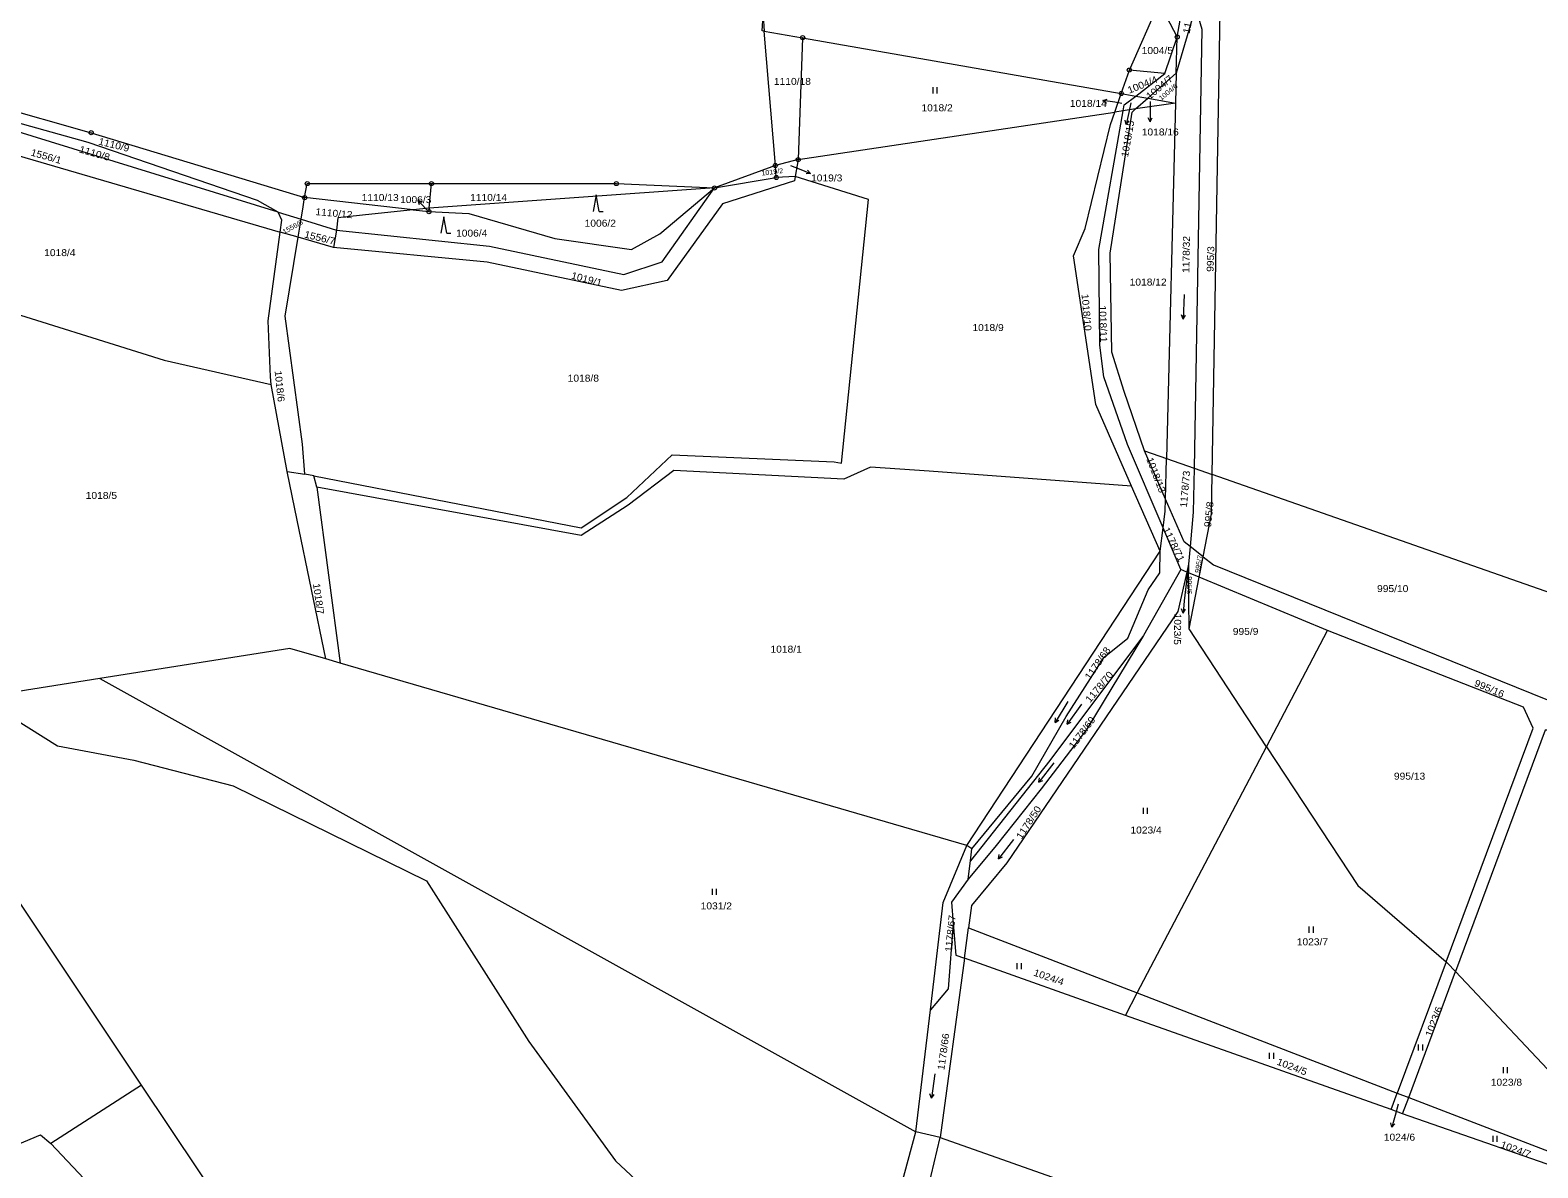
# Model space of a CAD drawing. Extents: x -686207 to -681951, y -1020493 to -1017811.
# Drawn here: x -684095.1 to -683726.8, y -1019774 to -1019496.1 of the extents above; entities that cross this region are included whole.
import ezdxf

# ---------------------------------------------------------------- set-up
doc = ezdxf.new("R2010")
doc.units = 0
doc.header["$LTSCALE"] = 0.4
for name, color, linetype, lineweight in [('1', 7, 'Continuous', 13), ('3', 7, 'Continuous', 13), ('4', 7, 'Continuous', 13), ('7', 7, 'Continuous', 13), ('8', 7, 'Continuous', 13)]:
    doc.layers.add(name, color=color, linetype=linetype, lineweight=lineweight)
doc.layers.add('2', color=7, linetype='Continuous')

msp = doc.modelspace()

# ---------------------------------------------------------------- linework, layer by layer
at = {"layer": '1'}
for p, q in [((-683814.9, -1019497.76), (-683812.99, -1019486.61)), ((-683913.08, -1019529.15), (-683915.78, -1019496.3)), ((-683915.78, -1019496.3), (-683906.41, -1019497.93)), ((-683906.41, -1019497.93), (-683828.58, -1019511.56)), ((-683817.9, -1019506.67), (-683814.9, -1019497.76)), ((-683828.58, -1019511.56), (-683826.6, -1019505.83)), ((-683817.9, -1019506.67), (-683826.6, -1019505.83)), ((-683815.13, -1019506.57), (-683822.07, -1019512.7)), ((-683815.13, -1019506.57), (-683815.33, -1019513.88)), ((-683825.05, -1019512.18), (-683817.9, -1019506.67)), ((-684142.57, -1019513.74), (-684034.05, -1019545.39)), ((-683830.16, -1019516.11), (-683828.58, -1019511.56)), ((-683815.33, -1019513.88), (-683825.06, -1019515.34)), ((-683815.33, -1019513.88), (-683817.52, -1019600.71)), ((-683828.13, -1019515.8), (-683830.16, -1019516.11)), ((-683825.06, -1019515.34), (-683828.13, -1019515.8)), ((-683907.51, -1019527.72), (-683913.08, -1019529.15)), ((-683907.51, -1019527.72), (-683908.25, -1019531.84)), ((-683913.08, -1019529.15), (-683927.95, -1019534.64)), ((-683912.84, -1019532.08), (-683913.08, -1019529.15)), ((-683908.25, -1019531.84), (-683912.84, -1019532.08)), ((-683997.61, -1019539.56), (-683997.09, -1019533.57)), ((-683927.95, -1019534.64), (-683997.61, -1019539.56)), ((-684001.58, -1019539.98), (-684028.07, -1019536.98)), ((-683997.61, -1019539.56), (-683997.69, -1019540.42)), ((-684034.55, -1019540.53), (-684028.9, -1019542.27)), ((-684029.63, -1019546.68), (-684034.05, -1019545.39)), ((-684020.26, -1019544.93), (-684020.98, -1019549.2)), ((-684032.36, -1019603.88), (-684036.21, -1019582.64)), ((-683822.89, -1019598.82), (-683817.52, -1019600.71)), ((-683817.77, -1019610.64), (-683822.89, -1019598.82)), ((-684032.36, -1019603.88), (-684028, -1019604.57)), ((-683711.76, -1019637.82), (-683806.4, -1019604.61)), ((-684025.12, -1019607.7), (-684019.38, -1019650.71)), ((-683819.09, -1019623.37), (-683826.09, -1019607.47)), ((-683819.09, -1019623.37), (-683818.37, -1019617.65)), ((-683814.03, -1019627.86), (-683818.37, -1019617.65)), ((-683866.34, -1019695.26), (-683819.09, -1019623.37)), ((-683808.59, -1019624.71), (-683811.75, -1019622.25)), ((-683814.03, -1019627.86), (-683823.16, -1019643.93)), ((-683812.14, -1019626.54), (-683812.58, -1019628.46)), ((-683812.14, -1019626.54), (-683812.12, -1019628.65)), ((-683809.55, -1019629.72), (-683808.59, -1019624.71)), ((-683809.55, -1019629.72), (-683812.12, -1019628.65)), ((-683811.99, -1019642.36), (-683812.12, -1019628.65)), ((-683811.99, -1019642.36), (-683809.55, -1019629.72)), ((-683778.18, -1019642.77), (-683809.55, -1019629.72)), ((-683793.07, -1019671.12), (-683811.99, -1019642.36)), ((-683793.07, -1019671.12), (-683778.18, -1019642.77)), ((-684078.12, -1019654.43), (-683878.77, -1019765.2)), ((-683824.66, -1019731.26), (-683793.07, -1019671.12)), ((-683866.91, -1019722.8), (-683865.91, -1019715.38)), ((-683865.91, -1019715.38), (-683824.66, -1019731.26)), ((-683749.22, -1019723.67), (-683761.17, -1019755.71)), ((-683758.36, -1019756.79), (-683746.94, -1019726.02)), ((-683827.54, -1019736.75), (-683824.66, -1019731.26)), ((-683824.66, -1019731.26), (-683761.17, -1019755.71)), ((-683878.77, -1019765.2), (-683875.2, -1019735.36)), ((-683762.67, -1019759.74), (-683827.54, -1019736.75)), ((-684067.91, -1019753.83), (-684090.05, -1019768.03)), ((-683762.67, -1019759.74), (-683761.17, -1019755.71)), ((-683761.17, -1019755.71), (-683758.36, -1019756.79)), ((-683759.84, -1019760.77), (-683758.36, -1019756.79)), ((-683758.36, -1019756.79), (-683713.6, -1019774.02)), ((-683759.84, -1019760.77), (-683762.67, -1019759.74)), ((-683872.8, -1019766.55), (-683878.77, -1019765.2))]:
    msp.add_line(p, q, dxfattribs=at)
for points in [[(-683806.4, -1019604.61), (-683804.42, -1019491.59), (-683808.55, -1019483.89)], [(-683826.6, -1019505.83), (-683819.34, -1019489.42), (-683814.9, -1019497.76)], [(-683810.47, -1019490.52), (-683815.13, -1019506.57), (-683814.9, -1019497.76)], [(-683810.47, -1019490.52), (-683808.87, -1019495.84), (-683810.8, -1019603.07)], [(-683906.41, -1019497.93), (-683907.51, -1019527.72), (-683830.16, -1019516.11)], [(-684141.85, -1019500.32), (-684128.34, -1019507.47), (-684080.22, -1019521.13), (-684028.07, -1019536.98)], [(-684034.55, -1019540.53), (-684039.57, -1019537.69), (-684080.94, -1019523.56), (-684132.64, -1019509.09), (-684140.7, -1019506.07)], [(-684034.55, -1019540.53), (-684140.33, -1019507.93), (-684140.7, -1019506.07)], [(-683828.58, -1019511.56), (-683825.05, -1019512.18), (-683822.07, -1019512.7)], [(-683828.13, -1019515.8), (-683827.87, -1019514.35), (-683825.05, -1019512.18)], [(-683825.06, -1019515.34), (-683822.07, -1019512.7), (-683815.33, -1019513.88)], [(-683826.09, -1019607.47), (-683834.81, -1019587.49), (-683840.23, -1019551.19), (-683837.43, -1019544.55), (-683831.21, -1019519.15), (-683830.16, -1019516.11)], [(-683818.37, -1019617.65), (-683827.02, -1019597.26), (-683832.84, -1019580.76), (-683833.78, -1019573.06), (-683834.09, -1019549.64), (-683828.13, -1019515.8)], [(-683822.89, -1019598.82), (-683827.86, -1019584.34), (-683830.85, -1019574.75), (-683831.32, -1019550.55), (-683825.94, -1019516.12), (-683825.06, -1019515.34)], [(-684025.86, -1019604.99), (-683960.5, -1019617.67), (-683949.37, -1019610.25), (-683938.27, -1019599.83), (-683898.73, -1019601.53), (-683896.93, -1019601.85), (-683890.32, -1019537.46), (-683908.25, -1019531.84)], [(-683908.25, -1019531.84), (-683908.44, -1019532.91), (-683925.96, -1019538.54), (-683939.48, -1019557.23), (-683950.67, -1019559.69), (-683983.44, -1019552.74), (-684020.98, -1019549.2)], [(-683997.09, -1019533.57), (-683951.91, -1019533.56), (-683927.95, -1019534.64), (-683912.84, -1019532.08)], [(-684028.07, -1019536.98), (-684027.43, -1019533.57), (-683997.09, -1019533.57)], [(-684020.26, -1019544.93), (-683982.91, -1019548.88), (-683950.09, -1019555.79), (-683940.73, -1019552.64), (-683927.95, -1019534.64)], [(-683997.69, -1019540.42), (-683987.93, -1019540.89), (-683966.98, -1019547), (-683948.22, -1019549.7), (-683941.34, -1019545.85), (-683927.95, -1019534.64)], [(-684028.9, -1019542.27), (-684028.4, -1019539.26), (-684028.07, -1019536.98)], [(-683997.61, -1019539.56), (-684001.58, -1019539.98), (-683997.69, -1019540.42)], [(-684034.05, -1019545.39), (-684033.65, -1019542.47), (-684034.55, -1019540.53)], [(-684020.98, -1019549.2), (-684029.63, -1019546.68), (-684028.9, -1019542.27), (-684020.26, -1019544.93)], [(-684001.58, -1019539.98), (-684011.63, -1019541.05), (-684019.94, -1019541.94), (-684020.26, -1019544.93)], [(-684036.21, -1019582.64), (-684036.41, -1019580.8), (-684037.02, -1019567.08), (-684034.05, -1019545.39)], [(-684028, -1019604.57), (-684028.6, -1019597.22), (-684032.85, -1019565.99), (-684029.63, -1019546.68)], [(-684134.44, -1019556), (-684107.16, -1019562.73), (-684062.39, -1019576.69), (-684036.21, -1019582.64)], [(-683818.37, -1019617.65), (-683817.85, -1019613.58), (-683817.77, -1019610.64), (-683817.52, -1019600.71), (-683810.8, -1019603.07), (-683806.4, -1019604.61)], [(-684022.93, -1019649.68), (-684029.92, -1019615.75), (-684032.36, -1019603.88)], [(-683826.09, -1019607.47), (-683875.54, -1019603.82), (-683889.8, -1019602.87), (-683896.36, -1019605.77), (-683937.9, -1019603.66), (-683949.07, -1019612.09), (-683960.49, -1019619.5), (-684025.12, -1019607.7), (-684025.86, -1019604.99), (-684028, -1019604.57)], [(-683810.8, -1019603.07), (-683810.99, -1019613.84), (-683811.75, -1019622.25), (-683812.14, -1019626.54)], [(-683808.59, -1019624.71), (-683806.57, -1019614.25), (-683806.4, -1019604.61)], [(-683811.75, -1019622.25), (-683813.25, -1019621.09), (-683817.77, -1019610.64)], [(-683865.07, -1019696.1), (-683850.42, -1019678.28), (-683842.05, -1019663.75), (-683832.72, -1019649.25), (-683827, -1019644.58), (-683822, -1019632.82), (-683819.19, -1019628.65), (-683819.09, -1019623.37)], [(-683812.12, -1019628.65), (-683812.58, -1019628.46), (-683814.03, -1019627.86)], [(-683808.59, -1019624.71), (-683806.08, -1019626.66), (-683724.42, -1019659.69)], [(-683812.58, -1019628.46), (-683814.79, -1019638.1), (-683856.51, -1019699.45), (-683865.18, -1019709.93), (-683865.91, -1019715.38)], [(-683749.22, -1019723.67), (-683727.96, -1019666.62), (-683730.3, -1019661.48), (-683778.18, -1019642.77)], [(-683823.16, -1019643.93), (-683837.01, -1019666.81), (-683848.12, -1019681.42), (-683859.1, -1019695.27), (-683865.97, -1019703.46)], [(-683823.16, -1019643.93), (-683846.03, -1019674.51), (-683865.43, -1019699.02)], [(-684022.93, -1019649.68), (-684031.7, -1019647.13), (-684078.12, -1019654.43)], [(-683865.97, -1019703.46), (-683865.43, -1019699.02), (-683865.07, -1019696.1), (-683866.34, -1019695.26), (-684019.38, -1019650.71), (-684022.93, -1019649.68)], [(-684078.12, -1019654.43), (-684107.33, -1019659.07), (-684119.47, -1019661)], [(-684067.91, -1019753.83), (-684114.88, -1019683.41), (-684124.65, -1019661.82)], [(-683721.48, -1019668.21), (-683722.82, -1019667.06), (-683725.06, -1019667.1), (-683746.94, -1019726.02)], [(-683793.07, -1019671.12), (-683770.77, -1019705.02), (-683749.22, -1019723.67)], [(-683875.2, -1019735.36), (-683872.08, -1019709.21), (-683866.34, -1019695.26)], [(-683865.97, -1019703.46), (-683870.03, -1019709.07), (-683869.62, -1019714.29)], [(-683869.62, -1019714.29), (-683870.83, -1019730.24), (-683875.2, -1019735.36)], [(-683869.62, -1019714.29), (-683869.01, -1019722.06), (-683866.91, -1019722.8)], [(-683827.54, -1019736.75), (-683866.91, -1019722.8), (-683872.8, -1019766.55)], [(-683749.22, -1019723.67), (-683748.86, -1019723.98), (-683746.94, -1019726.02)], [(-683746.94, -1019726.02), (-683719.16, -1019755.53), (-683705.93, -1019752.78)], [(-684027.91, -1019817.96), (-684025.91, -1019816.61), (-684067.91, -1019753.83)], [(-683688.64, -1019785.65), (-683713.55, -1019776.9), (-683759.84, -1019760.77)], [(-684104.89, -1019771.04), (-684092.56, -1019765.92), (-684090.05, -1019768.03)], [(-684090.05, -1019768.03), (-684080.65, -1019778.07), (-684044.24, -1019828.72)], [(-683872.8, -1019766.55), (-683782.67, -1019798.38), (-683709.96, -1019812.34), (-683687.92, -1019810.37), (-683671.13, -1019817.74), (-683653.49, -1019825.47)]]:
    msp.add_lwpolyline(points, dxfattribs=at)
msp.add_lwpolyline([(-683915.78, -1019496.3), (-683916.26, -1019496.21), (-683916.09, -1019492.57)], close=True, dxfattribs=at)
at = {"layer": '3'}
for p, q in [((-683874.511, -1019511.54), (-683874.511, -1019510.04)), ((-683873.51, -1019511.54), (-683873.51, -1019510.04)), ((-683956.11, -1019540.35), (-683955.114, -1019540.35)), ((-683993.33, -1019545.67), (-683992.334, -1019545.67)), ((-683813.424, -1019566.645), (-683813.891, -1019565.651)), ((-683844.751, -1019665.192), (-683844.678, -1019664.096)), ((-683841.83, -1019665.616), (-683841.662, -1019664.531)), ((-683848.754, -1019679.802), (-683848.548, -1019678.724)), ((-683823.181, -1019687.53), (-683823.181, -1019686.03)), ((-683822.18, -1019687.53), (-683822.18, -1019686.03)), ((-683858.574, -1019698.512), (-683858.368, -1019697.434)), ((-683928.431, -1019707.31), (-683928.431, -1019705.81)), ((-683927.43, -1019707.31), (-683927.43, -1019705.81)), ((-683782.651, -1019716.57), (-683782.651, -1019715.07)), ((-683781.65, -1019716.57), (-683781.65, -1019715.07)), ((-683853.981, -1019725.46), (-683853.981, -1019723.96)), ((-683852.98, -1019725.46), (-683852.98, -1019723.96)), ((-683792.341, -1019747.39), (-683792.341, -1019745.89)), ((-683791.34, -1019747.39), (-683791.34, -1019745.89)), ((-683755.941, -1019745.35), (-683755.941, -1019743.85)), ((-683754.94, -1019745.35), (-683754.94, -1019743.85)), ((-683735.201, -1019750.88), (-683735.201, -1019749.38)), ((-683734.2, -1019750.88), (-683734.2, -1019749.38)), ((-683874.948, -1019756.987), (-683875.309, -1019755.949)), ((-683737.721, -1019767.64), (-683737.721, -1019766.14)), ((-683736.72, -1019767.64), (-683736.72, -1019766.14))]:
    msp.add_line(p, q, dxfattribs=at)
for points in [[(-683956.11, -1019540.35), (-683956.86, -1019536.35), (-683957.61, -1019540.35)], [(-683993.33, -1019545.67), (-683994.08, -1019541.67), (-683994.83, -1019545.67)], [(-683813.214, -1019560.649), (-683813.424, -1019566.645), (-683812.889, -1019565.686)], [(-683841.661, -1019660.049), (-683844.751, -1019665.192), (-683843.818, -1019664.612)], [(-683838.304, -1019660.762), (-683841.83, -1019665.616), (-683840.85, -1019665.12)], [(-683845.06, -1019675.074), (-683848.754, -1019679.802), (-683847.758, -1019679.341)], [(-683854.88, -1019693.784), (-683858.574, -1019698.512), (-683857.578, -1019698.051)], [(-683874.113, -1019751.045), (-683874.948, -1019756.987), (-683874.316, -1019756.089)]]:
    msp.add_lwpolyline(points, dxfattribs=at)
at = {"layer": '4'}
for p, q in [((-684107.33, -1019659.07), (-684088.43, -1019670.93)), ((-684045.54, -1019680.66), (-683998.32, -1019703.86)), ((-683998.32, -1019703.86), (-683973.33, -1019743.11)), ((-683973.33, -1019743.11), (-683952.16, -1019772.25)), ((-683883.66, -1019783.4), (-683878.77, -1019765.2)), ((-683876.85, -1019783.53), (-683872.8, -1019766.55))]:
    msp.add_line(p, q, dxfattribs=at)
for points in [[(-684088.43, -1019670.93), (-684069.76, -1019674.41), (-684045.54, -1019680.66)], [(-683952.16, -1019772.25), (-683929.78, -1019793.16), (-683910.53, -1019808.81)]]:
    msp.add_lwpolyline(points, dxfattribs=at)
at = {"layer": '7'}
for p, q in [((-683833.084, -1019513.241), (-683832.173, -1019513.892)), ((-683826.23, -1019513.81), (-683826.74, -1019516.19)), ((-683821.52, -1019513.54), (-683821.51, -1019515.48)), ((-683821.51, -1019518.481), (-683821.009, -1019517.48)), ((-683827.364, -1019519.125), (-683826.666, -1019518.25)), ((-683904.468, -1019531.094), (-683905.208, -1019530.255)), ((-684000.388, -1019537.58), (-684000.09, -1019538.659)), ((-683998.07, -1019540.16), (-683998.38, -1019539.81)), ((-683812.32, -1019627.93), (-683813.17, -1019635.49)), ((-683813.484, -1019638.475), (-683812.881, -1019637.531)), ((-683762.517, -1019764.065), (-683761.76, -1019763.24))]:
    msp.add_line(p, q, dxfattribs=at)
for points in [[(-683828.43, -1019513.99), (-683830.12, -1019513.71), (-683833.084, -1019513.241), (-683832.017, -1019512.903)], [(-683826.74, -1019516.19), (-683827.364, -1019519.125), (-683827.646, -1019518.042)], [(-683821.51, -1019515.48), (-683821.51, -1019518.481), (-683822.011, -1019517.48)], [(-683909.37, -1019529.13), (-683907.25, -1019529.97), (-683904.468, -1019531.094), (-683905.584, -1019531.183)], [(-683998.38, -1019539.81), (-684000.388, -1019537.58), (-683999.346, -1019537.989)], [(-683813.17, -1019635.49), (-683813.484, -1019638.475), (-683813.877, -1019637.426)], [(-683760.9, -1019758.44), (-683761.69, -1019761.18), (-683762.517, -1019764.065), (-683762.722, -1019762.964)]]:
    msp.add_lwpolyline(points, dxfattribs=at)
at = {"layer": '8'}
for centre, radius in [((-683906.41, -1019497.9299), 0.5), ((-683906.41, -1019497.9299), 0.0303), ((-683814.9, -1019497.7599), 0.5), ((-683814.9, -1019497.7599), 0.0303), ((-683826.6, -1019505.8299), 0.5), ((-683826.6, -1019505.8299), 0.0303), ((-683828.58, -1019511.5599), 0.5), ((-683828.58, -1019511.5599), 0.0303), ((-684080.22, -1019521.1299), 0.5), ((-684080.22, -1019521.1299), 0.0303), ((-683913.08, -1019529.1499), 0.5), ((-683907.51, -1019527.7199), 0.5), ((-683907.51, -1019527.7199), 0.0303), ((-683912.84, -1019532.0799), 0.5), ((-683913.08, -1019529.1499), 0.0303), ((-683912.84, -1019532.0799), 0.0303), ((-684027.43, -1019533.5699), 0.5), ((-684027.43, -1019533.5699), 0.0303), ((-683997.09, -1019533.5699), 0.5), ((-683997.09, -1019533.5699), 0.0303), ((-683951.91, -1019533.5599), 0.5), ((-683951.91, -1019533.5599), 0.0303), ((-683927.95, -1019534.6399), 0.5), ((-683927.95, -1019534.6399), 0.0303), ((-684028.07, -1019536.9799), 0.5), ((-684028.07, -1019536.9799), 0.0303), ((-683997.69, -1019540.4199), 0.5), ((-683997.69, -1019540.4199), 0.0303)]:
    msp.add_circle(centre, radius, dxfattribs=at)

# ---------------------------------------------------------------- texts
at = {"layer": '2', "width": 1.1}
for s, height, rotation, p in [('1178/72', 1.7, 79, (-683811.885, -1019497.042)), ('1004/4', 1.7, 22, (-683826.631, -1019511.628)), ('1004/7', 1.7, 40, (-683821.633, -1019513.131)), ('1004/6', 1.19, 40, (-683818.777, -1019513.355)), ('1018/15', 1.7, 80, (-683826.942, -1019527.221)), ('1110/8', 1.7, 344, (-684083.294, -1019525.907)), ('1110/9', 1.7, 346, (-684078.565, -1019523.994)), ('1556/1', 1.7, 344, (-684095.114, -1019526.667)), ('1019/2', 1.19, 7, (-683916.417, -1019531.62)), ('1110/12', 1.7, 355, (-684025.484, -1019541.246)), ('1556/6', 1.19, 29, (-684033.051, -1019545.95)), ('1556/7', 1.7, 346, (-684028.275, -1019546.694)), ('1178/32', 1.7, 89, (-683811.95, -1019555.404)), ('995/3', 1.7, 88, (-683806.04, -1019555.149)), ('1019/1', 1.7, 345, (-683963.079, -1019556.731)), ('1018/10', 1.7, 275, (-683838.286, -1019560.584)), ('1018/11', 1.7, 272, (-683833.999, -1019563.369)), ('1018/6', 1.7, 276, (-684035.405, -1019579.358)), ('1018/13', 1.7, 291, (-683822.483, -1019600.834)), ('1178/73', 1.7, 85, (-683812.553, -1019612.774)), ('995/8', 1.7, 84, (-683806.664, -1019617.568)), ('1178/71', 1.7, 296, (-683818.473, -1019618.012)), ('995/7', 1.19, 80, (-683809.454, -1019628.753)), ('1018/7', 1.7, 278, (-684026.041, -1019631.338)), ('995/5', 1.19, 269, (-683812.494, -1019629.479)), ('1023/5', 1.7, 269, (-683815.602, -1019638.59)), ('1178/68', 1.7, 55, (-683836.263, -1019654.907)), ('1178/70', 1.7, 50, (-683836.208, -1019660.516)), ('995/16', 1.7, 337, (-683742.512, -1019656.192)), ('1178/69', 1.7, 53, (-683840.201, -1019671.791)), ('1178/50', 1.7, 57, (-683852.947, -1019693.872)), ('1178/67', 1.7, 84, (-683869.964, -1019721.328)), ('1024/4', 1.7, 341, (-683850.166, -1019726.983)), ('1023/6', 1.7, 69, (-683752.806, -1019742.114)), ('1178/66', 1.7, 82, (-683871.808, -1019750.208)), ('1024/5', 1.7, 339, (-683790.734, -1019748.723)), ('1024/7', 1.7, 340, (-683736.09, -1019768.968))]:
    msp.add_text(s, height=height, rotation=rotation, dxfattribs=at).set_placement(p)
for s, p in [('1004/5', (-683823.59, -1019501.91)), ('1110/18', (-683913.43, -1019509.45)), ('1018/14', (-683841.136, -1019514.82)), ('1018/2', (-683877.39, -1019515.9)), ('1018/16', (-683823.57, -1019521.809)), ('1019/3', (-683904.361, -1019533.039)), ('1110/13', (-684014.14, -1019537.82)), ('1110/14', (-683987.65, -1019537.809)), ('1006/3', (-684004.75, -1019538.323)), ('1006/2', (-683959.67, -1019544.09)), ('1006/4', (-683991.08, -1019546.52)), ('1018/4', (-684091.7, -1019551.28)), ('1018/12', (-683826.53, -1019558.47)), ('1018/9', (-683864.94, -1019569.59)), ('1018/8', (-683963.81, -1019581.94)), ('1018/5', (-684081.55, -1019610.59)), ('995/10', (-683766.09, -1019633.35)), ('995/9', (-683801.33, -1019643.809)), ('1018/1', (-683914.27, -1019648.14)), ('995/13', (-683761.97, -1019679.16)), ('1023/4', (-683826.34, -1019692.32)), ('1031/2', (-683931.325, -1019710.86)), ('1023/7', (-683785.7, -1019719.62)), ('1023/8', (-683738.31, -1019753.929)), ('1024/6', (-683764.44, -1019767.353))]:
    msp.add_text(s, height=1.7, dxfattribs=at).set_placement(p)

doc.saveas('drawing.dxf')
